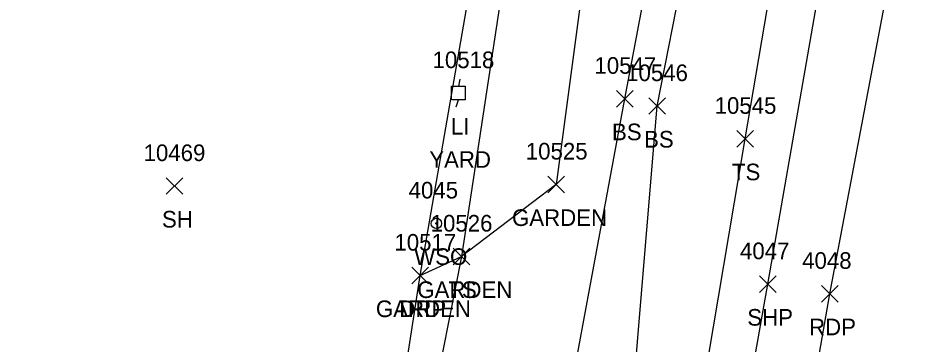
# Model space of a CAD drawing. Extents: x 1769141 to 1770911, y 735471 to 741449.
# Drawn here: x 1770501.4 to 1770609.7, y 738773.6 to 738812.8 of the extents above; entities that cross this region are included whole.
import ezdxf

# ---------------------------------------------------------------- set-up
doc = ezdxf.new("R2010")
doc.units = 0
for name, color, linetype in [('L_A', 7, 'Continuous'), ('L_I', 7, 'Continuous'), ('L_TIC', 7, 'Continuous'), ('LAPB', 7, 'Continuous'), ('LELB', 7, 'Continuous'), ('P_A', 7, 'Continuous'), ('P_I', 7, 'Continuous'), ('P_TIC', 7, 'Continuous'), ('PET', 7, 'Continuous'), ('PSP', 7, 'Continuous'), ('R_A', 7, 'Continuous'), ('R_I', 7, 'Continuous'), ('R_TIC', 7, 'Continuous'), ('RDP', 7, 'Continuous'), ('U_A', 7, 'Continuous'), ('U_C', 7, 'Continuous'), ('U_I', 7, 'Continuous'), ('ULP', 7, 'Continuous'), ('UWV', 7, 'Continuous')]:
    doc.layers.add(name, color=color, linetype=linetype)

msp = doc.modelspace()

# ---------------------------------------------------------------- linework, layer by layer
at = {"layer": 'L_TIC'}
for points in [[(1770573.46, 738802.11), (1770575.46, 738804.11)], [(1770575.46, 738802.11), (1770573.46, 738804.11)], [(1770577.32, 738801.23), (1770579.32, 738803.23)], [(1770579.32, 738801.23), (1770577.32, 738803.23)], [(1770587.92, 738797.29), (1770589.92, 738799.29)], [(1770589.92, 738797.29), (1770587.92, 738799.29)], [(1770519.26, 738791.6), (1770521.26, 738793.6)], [(1770521.26, 738791.6), (1770519.26, 738793.6)], [(1770565.2, 738791.79), (1770567.2, 738793.79)], [(1770567.2, 738791.79), (1770565.2, 738793.79)], [(1770553.8, 738783.12), (1770555.8, 738785.12)], [(1770555.8, 738783.12), (1770553.8, 738785.12)], [(1770553.8, 738783.12), (1770555.8, 738785.12)], [(1770555.8, 738783.12), (1770553.8, 738785.12)], [(1770553.8, 738783.12), (1770555.8, 738785.12)], [(1770555.8, 738783.12), (1770553.8, 738785.12)], [(1770548.82, 738780.82), (1770550.82, 738782.82)], [(1770550.82, 738780.82), (1770548.82, 738782.82)]]:
    msp.add_lwpolyline(points, dxfattribs=at)
at = {"layer": 'LAPB'}
for points in [[(1770571.53, 738842.75), (1770575.17, 738835.11), (1770574.45, 738828.42), (1770569.87, 738820.52), (1770566.2, 738792.79), (1770554.8, 738784.12)], [(1770549.82, 738781.82), (1770554.8, 738784.12)]]:
    msp.add_lwpolyline(points, dxfattribs=at)
at = {"layer": 'LELB'}
for points in [[(1770566.96, 738697.08), (1770575.07, 738717.89), (1770581.92, 738756.59), (1770588.92, 738798.29), (1770594.89, 738833.47), (1770593.49, 738851.06), (1770582.86, 738862.01)], [(1770561.14, 738692.42), (1770567.59, 738720.64), (1770574.55, 738757.07), (1770578.32, 738802.23), (1770584.83, 738835.33), (1770578.79, 738853.79)], [(1770558.1, 738692.42), (1770560.99, 738721.79), (1770565.49, 738754.78), (1770574.46, 738803.11), (1770580.6, 738835.61), (1770576.84, 738850.13)], [(1770562.44, 738834.62), (1770554.8, 738784.12), (1770551.05, 738765.27), (1770544.81, 738718.39)]]:
    msp.add_lwpolyline(points, dxfattribs=at)
at = {"layer": 'P_TIC'}
for points in [[(1770590.64, 738779.79), (1770592.64, 738781.79)], [(1770592.64, 738779.79), (1770590.64, 738781.79)], [(1770598.12, 738778.63), (1770600.12, 738780.63)], [(1770600.12, 738778.63), (1770598.12, 738780.63)]]:
    msp.add_lwpolyline(points, dxfattribs=at)
at = {"layer": 'PET'}
msp.add_lwpolyline([(1770498.35, 738202.33), (1770505.32, 738243.58), (1770514, 738293.39), (1770521.19, 738334.51), (1770529.87, 738384.51), (1770540.37, 738444.39), (1770550.2, 738502.07), (1770560.29, 738558.86), (1770568.53, 738606.15), (1770576.04, 738648.17), (1770584.13, 738693.97), (1770592.27, 738740.2), (1770599.12, 738779.63), (1770606.64, 738819.52), (1770613.62, 738858.77), (1770620.19, 738893.47), (1770628.38, 738936.17), (1770637.53, 738984.97), (1770643.72, 739017.75), (1770651.2, 739057.47)], dxfattribs=at)
at = {"layer": 'PSP'}
msp.add_lwpolyline([(1770492.13, 738203.4), (1770499.17, 738244.91), (1770502.67, 738268.32), (1770507.12, 738294.16), (1770515.22, 738335.86), (1770523.37, 738385.12), (1770531.43, 738446.08), (1770541.85, 738504.16), (1770552.67, 738560.33), (1770559.53, 738607.65), (1770567.71, 738649.42), (1770576.6, 738695.75), (1770584.51, 738740.49), (1770591.64, 738780.79), (1770598.7, 738821.32), (1770605.59, 738859.98), (1770618.05, 738920.67), (1770621.75, 738939.17), (1770631.13, 738987.07), (1770635.84, 739018.16), (1770643.49, 739059.41)], dxfattribs=at)
at = {"layer": 'R_TIC'}
for points in [[(1770548.82, 738780.82), (1770550.82, 738782.82)], [(1770550.82, 738780.82), (1770548.82, 738782.82)]]:
    msp.add_lwpolyline(points, dxfattribs=at)
at = {"layer": 'RDP'}
msp.add_lwpolyline([(1770547.61, 738767.5), (1770549.82, 738781.82), (1770559.12, 738835.45)], dxfattribs=at)
at = {"layer": 'ULP'}
for p, q in [((1770554.58, 738805.46), (1770554.42, 738804.63)), ((1770553.58, 738802.96), (1770553.58, 738804.63)), ((1770553.58, 738804.63), (1770555.25, 738804.63)), ((1770555.25, 738804.63), (1770555.25, 738802.96)), ((1770555.25, 738802.96), (1770553.58, 738802.96)), ((1770554.17, 738802.13), (1770554.42, 738802.96)), ((1770554.42, 738803.79), (1770554.42, 738803.79))]:
    msp.add_line(p, q, dxfattribs=at)
at = {"layer": 'UWV'}
for radius in [0.625, 0.0833]:
    msp.add_circle((1770551.77, 738788.1), radius, dxfattribs=at)

# ---------------------------------------------------------------- texts
at = {"layer": 'L_A'}
for s, p in [('BS', (1770572.9, 738798.11)), ('BS', (1770576.76, 738797.23)), ('TS', (1770587.33, 738793.29)), ('GARDEN', (1770560.87, 738787.79)), ('SH', (1770518.75, 738787.6)), ('GARDEN', (1770549.47, 738779.12)), ('GARDEN', (1770549.47, 738779.12)), ('TS', (1770553.21, 738779.12)), ('GARDEN', (1770544.49, 738776.82))]:
    msp.add_text(s, height=2, dxfattribs=at).set_placement(p)
at = {"layer": 'L_I'}
for s, p in [('10547', (1770570.79, 738806.11)), ('10546', (1770574.6, 738805.23)), ('10545', (1770585.25, 738801.29)), ('10469', (1770516.54, 738795.6)), ('10525', (1770562.53, 738795.79)), ('10526', (1770551.08, 738787.12)), ('10526', (1770551.08, 738787.12)), ('10526', (1770551.08, 738787.12)), ('10517', (1770546.72, 738784.82))]:
    msp.add_text(s, height=2, dxfattribs=at).set_placement(p)
at = {"layer": 'P_A'}
for s, p in [('SHP', (1770589.18, 738775.79)), ('RDP', (1770596.61, 738774.63))]:
    msp.add_text(s, height=2, dxfattribs=at).set_placement(p)
at = {"layer": 'P_I'}
for s, p in [('4047', (1770588.3, 738783.79)), ('4048', (1770595.78, 738782.63))]:
    msp.add_text(s, height=2, dxfattribs=at).set_placement(p)
at = {"layer": 'R_A'}
msp.add_text('DRP', height=2, dxfattribs=at).set_placement((1770547.31, 738776.82))
at = {"layer": 'R_I'}
msp.add_text('10517', height=2, dxfattribs=at).set_placement((1770546.72, 738784.82))
at = {"layer": 'U_A'}
for s, p in [('LI', (1770553.52, 738798.79)), ('WSO', (1770549.1, 738783.1))]:
    msp.add_text(s, height=2, dxfattribs=at).set_placement(p)
at = {"layer": 'U_C'}
msp.add_text('YARD', height=2, dxfattribs=at).set_placement((1770550.91, 738794.79))
at = {"layer": 'U_I'}
for s, p in [('10518', (1770551.31, 738806.79)), ('4045', (1770548.43, 738791.1))]:
    msp.add_text(s, height=2, dxfattribs=at).set_placement(p)

doc.saveas('drawing.dxf')
